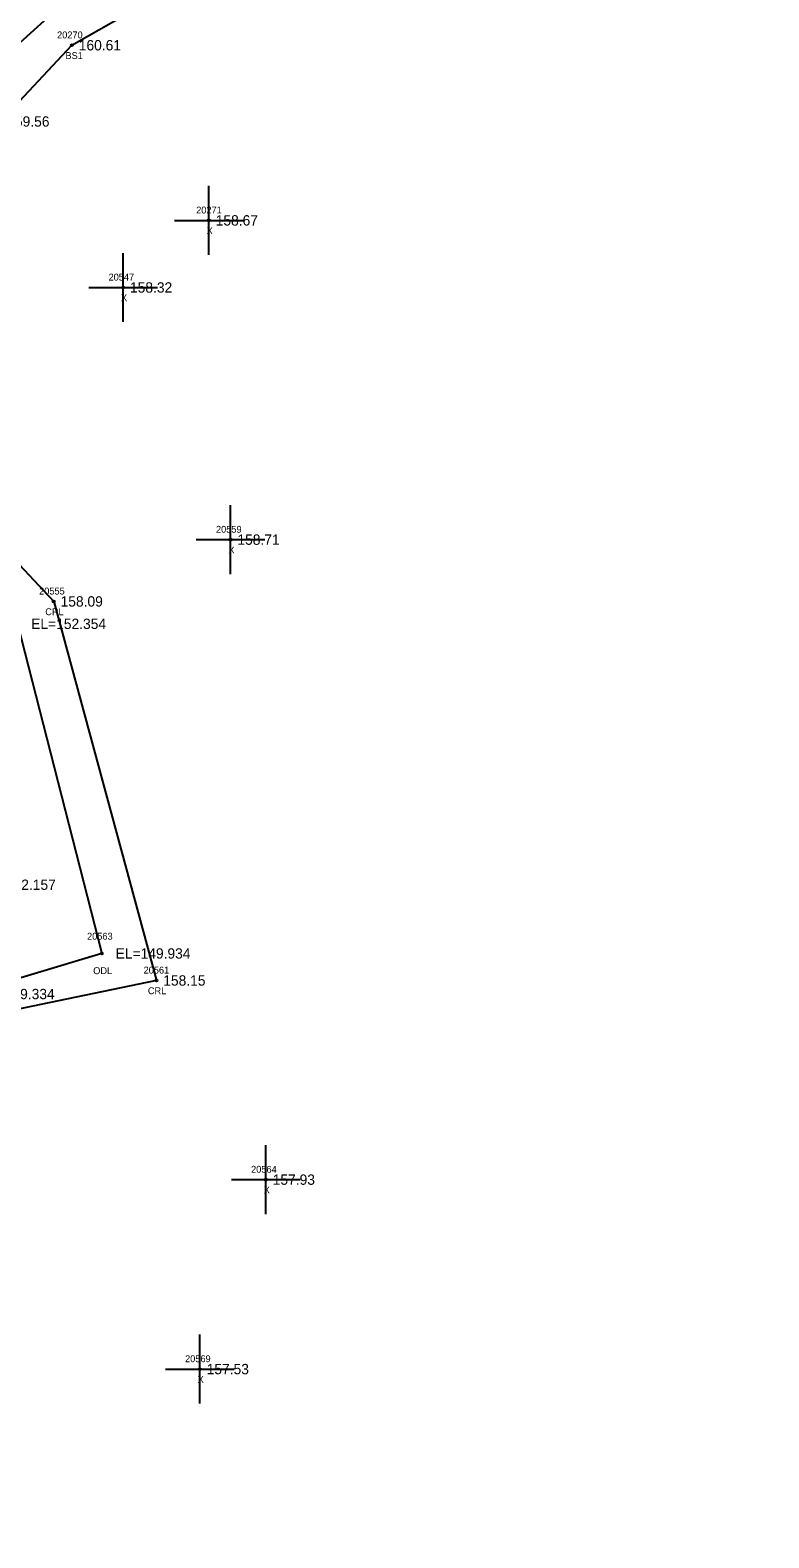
# Model space of a CAD drawing. Extents: x 2279528 to 2280976, y 1061373 to 1062235.
# Drawn here: x 2280317.1 to 2280424.4, y 1061599.1 to 1061818 of the extents above; entities that cross this region are included whole.
import ezdxf

# ---------------------------------------------------------------- set-up
doc = ezdxf.new("R2010")
doc.units = 0
for name, color, linetype in [('RD_DTM_BkLn2', 7, 'Continuous'), ('RD_DTM_BkLn_txCode', 7, 'Continuous'), ('RD_EX_H2O', 7, 'Continuous'), ('RD_EX_H2O_txCode', 7, 'Continuous'), ('RD_EX_Misc', 7, 'Continuous'), ('RD_EX_Misc_txCode', 7, 'Continuous'), ('RD_EX_TX_H2O_ELEV', 7, 'Continuous'), ('RD_EX_TX_Misc_ELEV', 7, 'Continuous'), ('RD_SMD_Locator', 7, 'Continuous')]:
    doc.layers.add(name, color=color, linetype=linetype)

msp = doc.modelspace()

# ---------------------------------------------------------------- linework, layer by layer
at = {"layer": 'RD_DTM_BkLn2'}
for points in [[(2280272.88, 1061795.9), (2280297.58, 1061791.78), (2280309.49, 1061810.68), (2280320.64, 1061820.76), (2280406.65, 1061872.9), (2280496.79, 1061919.98), (2280582.43, 1061964.41), (2280663.95, 1062011.32), (2280685.25, 1062021.45), (2280750.74, 1062056.04), (2280766.13, 1062062.47), (2280799.22, 1062079.83)], [(2280270.02, 1061790.74), (2280279.94, 1061788.98), (2280298.7, 1061789.36), (2280312.74, 1061804.74), (2280323.13, 1061815.81), (2280411.42, 1061866.03), (2280499.93, 1061915.08), (2280584.56, 1061957.49), (2280666.91, 1062006.18), (2280674.46, 1062011.72), (2280685.18, 1062009.25), (2280689.93, 1062011.32), (2280693.25, 1062019.83), (2280753.26, 1062052.49), (2280766.38, 1062057.83), (2280800.29, 1062072.08)]]:
    msp.add_lwpolyline(points, dxfattribs=at)
at = {"layer": 'RD_EX_H2O'}
for points in [[(2280243.56, 1061789.13), (2280258.67, 1061797.27), (2280267.66, 1061787.82), (2280287.8, 1061761.36), (2280315.22, 1061731.8), (2280327.48, 1061683.93), (2280307.76, 1061678.04), (2280294.04, 1061661.65), (2280295.74, 1061631.81), (2280310.81, 1061587.94), (2280304.48, 1061546.39), (2280272.84, 1061527.93), (2280259.98, 1061540.36), (2280245.21, 1061537.05), (2280265.99, 1061500.75), (2280299.66, 1061476.28), (2280353.73, 1061471.3), (2280375.17, 1061457.42), (2280376.85, 1061433.19), (2280358.1, 1061419.49), (2280333.32, 1061393.34)], [(2280269.9, 1061794.49), (2280270.02, 1061790.74), (2280293.77, 1061763.48), (2280320.49, 1061735.05), (2280335.4, 1061680.01), (2280309.48, 1061674.63), (2280300.03, 1061660.41), (2280304.47, 1061633.12), (2280315.65, 1061587.64), (2280305.89, 1061543.57), (2280270.77, 1061524.54), (2280257.61, 1061536.28), (2280249.22, 1061535.26), (2280269.33, 1061502.83), (2280301.34, 1061480.02), (2280355.94, 1061475.37), (2280377.91, 1061459.94), (2280379.03, 1061433), (2280360.13, 1061417.18), (2280333.79, 1061387.95)]]:
    msp.add_lwpolyline(points, dxfattribs=at)
at = {"layer": 'RD_EX_Misc'}
for p, q in [((2280343.02, 1061785.38), (2280343.02, 1061795.38)), ((2280338.02, 1061790.38), (2280348.02, 1061790.38)), ((2280330.57, 1061775.64), (2280330.57, 1061785.64)), ((2280325.57, 1061780.64), (2280335.57, 1061780.64)), ((2280346.17, 1061739.02), (2280346.17, 1061749.02)), ((2280341.17, 1061744.02), (2280351.17, 1061744.02)), ((2280351.3, 1061646.09), (2280351.3, 1061656.09)), ((2280346.3, 1061651.09), (2280356.3, 1061651.09)), ((2280341.71, 1061618.58), (2280341.71, 1061628.58)), ((2280336.71, 1061623.58), (2280346.71, 1061623.58))]:
    msp.add_line(p, q, dxfattribs=at)
at = {"layer": 'RD_SMD_Locator'}
for centre in [(2280323.13, 1061815.81), (2280343.02, 1061790.38), (2280330.57, 1061780.64), (2280346.17, 1061744.02), (2280320.49, 1061735.05), (2280327.48, 1061683.93), (2280335.4, 1061680.01), (2280351.3, 1061651.09), (2280341.71, 1061623.58)]:
    msp.add_circle(centre, 0.15, dxfattribs=at)

# ---------------------------------------------------------------- texts
at = {"layer": 'RD_DTM_BkLn_txCode'}
for s, p in [('20270', (2280320.98, 1061816.81)), ('BS1', (2280322.19, 1061813.81))]:
    msp.add_text(s, height=1, dxfattribs=at).set_placement(p)
at = {"layer": 'RD_EX_H2O_txCode'}
for s, p in [('20555', (2280318.37, 1061736.05)), ('CRL', (2280319.26, 1061733.05)), ('20563', (2280325.33, 1061685.93)), ('ODL', (2280326.23, 1061680.93)), ('20561', (2280333.54, 1061681.01)), ('CRL', (2280334.17, 1061678.01))]:
    msp.add_text(s, height=1, dxfattribs=at).set_placement(p)
at = {"layer": 'RD_EX_Misc_txCode'}
for s, p in [('20271', (2280341.18, 1061791.38)), ('X', (2280342.7, 1061788.38)), ('20547', (2280328.45, 1061781.64)), ('X', (2280330.26, 1061778.64)), ('20559', (2280344.06, 1061745.02)), ('X', (2280345.86, 1061742.02)), ('20564', (2280349.16, 1061652.09)), ('X', (2280350.99, 1061649.09)), ('20569', (2280339.57, 1061624.58)), ('X', (2280341.39, 1061621.58))]:
    msp.add_text(s, height=1, dxfattribs=at).set_placement(p)
at = {"layer": 'RD_EX_TX_H2O_ELEV'}
for s, p in [('158.09', (2280321.49, 1061734.3)), ('EL=152.354', (2280317.22, 1061731.05)), ('EL=152.157', (2280309.92, 1061693.16)), ('EL=149.934', (2280329.48, 1061683.18)), ('158.15', (2280336.4, 1061679.26)), ('EL=149.334', (2280309.76, 1061677.29))]:
    msp.add_text(s, height=1.5, dxfattribs=at).set_placement(p)
at = {"layer": 'RD_EX_TX_Misc_ELEV'}
for s, p in [('160.61', (2280324.13, 1061815.06)), ('159.56', (2280313.74, 1061803.99)), ('158.67', (2280344.02, 1061789.63)), ('158.32', (2280331.57, 1061779.89)), ('158.71', (2280347.17, 1061743.27)), ('157.93', (2280352.3, 1061650.34)), ('157.53', (2280342.71, 1061622.83))]:
    msp.add_text(s, height=1.5, dxfattribs=at).set_placement(p)

doc.saveas('drawing.dxf')
